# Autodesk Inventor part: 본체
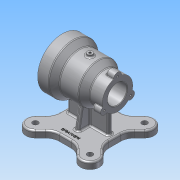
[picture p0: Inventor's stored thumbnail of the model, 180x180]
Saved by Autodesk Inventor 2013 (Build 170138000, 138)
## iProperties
Created: 2017-03
Part Number: 본체
Material: 알루미늄 6061
Document SubType Name: Modeling
Designer: Administrator
Density: 2.71 g/cm^3
Mass: 1005.19 g
Surface Area: 839.933 cm^2
Volume: 370.92 cm^3
Author: Administrator
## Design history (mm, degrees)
sketch "스케치1"
  geometry: L1 (-48, 0)-(52, 0); L2 (52, 0)-(52, 27.5); L3 (52, 27.5)-(29, 27.5); L4 (29, 27.5)-(17, 36); L5 (17, 36)-(-17, 36); L6 (-17, 36)-(-28, 45); L7 (-28, 45)-(-48, 45); L8 (-48, 45)-(-48, 0); 2 further points
  constraints: 16 end point, 3 parallel, 2 perpendicular, 1 horizontal, 1 midpoint, 1 point on line, 1 vertical alignment
  dimensions: "d9" = 55 diameter of L3 L1; "d11" = 72 diameter of L5 L1; "d12" = 90 diameter of L7 L1; "d14" = 23 distance of L2.end L3.end; "d15" = 100 distance between parallel lines of L2 L8; "d16" = 20 distance of L6.end L7.end; "d17" = 31 distance from line of L5.end L8; "d18" = 65 distance from line of L4.end L8
revolve "회전1" sketch "스케치1" stored, may be unused: angle "d19" = 90 deg
hole "구멍1" diameter "d22" = 52; stored, may be unused: countersink angle "d26" = 90 deg, drill point angle "d28" = 0 deg; dims "d20" = 10, "d21" = 10, "d23" = 6, "d24" = 70, "d25" = 23, "d27" = 70
hole "구멍2" diameter "d31" = 35; stored, may be unused: countersink angle "d35" = 90 deg, drill point angle "d37" = 0 deg; dims "d29" = 10, "d30" = 10, "d32" = 6, "d33" = 70, "d34" = 23, "d36" = 30
chamfer "모따기1" distance "d38" = 1; stored, may be unused: second distance "d39" = 2, angle "d40" = 45 deg
fillet "모깎기1" dims "d41" = 3
fillet "모깎기2" dims "d42" = 3
node "작업 평면1"
node "작업 평면3"
sketch "스케치11"
  geometry: L1 (-18.958, 45)-(22.958, 45); L2 (22.958, 45)-(39.477, 61.518); L3 (63.518, 37.477)-(47, 20.958); L4 (47, 20.958)-(47, -20.958); L5 (47, -20.958)-(63.518, -37.477); L6 (39.477, -61.518)-(22.958, -45); L7 (22.958, -45)-(-18.958, -45); L8 (-18.958, -45)-(-35.477, -61.518); L9 (-59.518, -37.477)-(-43, -20.958); L10 (-43, -20.958)-(-43, 20.958); L11 (-43, 20.958)-(-59.518, 37.477); L12 (-35.477, 61.518)-(-18.958, 45); L13 (0, 0)-(2, 0); L14 (2, 0)-(-47.497, 49.497); L15 (2, 0)-(51.497, 49.497); L16 (2, 0)-(-47.497, -49.497); L17 (2, 0)-(51.497, -49.497); A1 r 17 centre (51.497, 49.497) between (63.518, 37.477) and (39.477, 61.518); A2 r 17 centre (51.497, -49.497) between (39.477, -61.518) and (63.518, -37.477); A3 r 17 centre (-47.497, -49.497) between (-59.518, -37.477) and (-35.477, -61.518); A4 r 17 centre (-47.497, 49.497) between (-35.477, 61.518) and (-59.518, 37.477); 2 further points
  constraints: 34 end point, 8 point on circle, 8 tangent, 5 equal length, 5 perpendicular, 4 centre point, 2 equal radius, 2 parallel, 1 coincident, 1 horizontal, 1 midpoint, 1 vertical alignment
  dimensions: "d179" = 2 distance of L13.start L13.end; "d182" = 17 radius of A1; "d183" = 90 distance between parallel lines of L7 L1; "d184" = 45 distance from line of L13.end L7; "d185" = 90 distance between parallel lines of L4 L10; "d186" = 45 distance from line of L13.end L10; "d187" = 70 distance of L13.end L14.end; "d188" = 70 distance of L13.end L15.end; "d189" = 90 deg angle of L15 L14; "d191" = 70 distance of L13.end L16.end; "d192" = 70 distance of L13.end L17.end; "d193" = 90 deg angle of L15 L17; "d194" = 90 deg angle of L16 L17; "d195" = 34 distance between parallel lines of L9 L8
extrude "돌출6" join sketch "스케치11" distance "d196" = 12; taper "d197" = 0 deg
sketch "스케치3"
  geometry: C1 r 5 at (-47.497, -49.497); C2 r 5 at (51.497, -49.497); C3 r 5 at (51.497, 49.497); C4 r 5 at (-47.497, 49.497); A1 r 17 centre (-47.497, -49.497) between (-59.518, -37.477) and (-35.477, -61.518) reference; A2 r 17 centre (51.497, -49.497) between (39.477, -61.518) and (63.518, -37.477) reference; A3 r 17 centre (51.497, 49.497) between (63.518, 37.477) and (39.477, 61.518) reference; A4 r 17 centre (-47.497, 49.497) between (-35.477, 61.518) and (-59.518, 37.477) reference; 1 further point
  constraints: 4 centre point, 4 coincident, 1 equal radius
  dimensions: "d72" = 10 diameter of C1; "d198" = 10 diameter of C3; "d199" = 10 diameter of C4
extrude "돌출2" cut sketch "스케치3" distance "d74" = 12; taper "d75" = 0 deg
fillet "모깎기11" dims "d200" = 25
fillet "모깎기12" dims "d201" = 3
sketch "스케치12"
  geometry: L1 (-35, 4)-(39, 4); L2 (39, 4)-(39, -4); L3 (39, -4)-(-35, -4); L4 (-35, -4)-(-35, 4); L5 (0, 0)-(2, 0)
  constraints: 10 end point, 2 parallel, 2 perpendicular, 1 horizontal
  dimensions: "d231" = 2 distance of L5.start L5.end; "d232" = 8 distance between parallel lines of L3 L1; "d233" = 74 distance of L2.end L3.end; "d234" = 37 distance from line of L5.end L4; "d235" = 4 distance from line of L5.end L1
extrude "돌출7" join sketch "스케치12" stored distance "d207" = 12; taper "d208" = 0 deg
node "작업 평면4"
sketch "스케치14"
  geometry: L1 (-42, -70)-(-4, -70) reference; L2 (-4, -70)-(-4, -35.777) reference; L3 (4, -35.777)-(4, -70) reference; L4 (4, -70)-(42, -70) reference; L5 (45, -73)-(45, -82) reference; L6 (45, -82)-(-45, -82) reference; L7 (-45, -82)-(-45, -73) reference; L8 (-25, -70)-(-21.244, -48.697); L9 (25, -70)-(21.849, -52.131); C1 r 26 at (0, 0) reference; A1 r 3 centre (-42, -73) between (-42, -70) and (-45, -73) reference; A2 r 36 centre (0, 0) between (4, -35.777) and (-4, -35.777) reference; A3 r 3 centre (42, -73) between (45, -73) and (42, -70) reference; 1 further point
  constraints: 4 end point, 2 point on line
  dimensions: "d237" = 25 horizontal distance of point (0, 0) L9.start; "d238" = 25 horizontal distance of point (0, 0) L8.start; "d239" = 100 deg angle of L4 L9; "d240" = 100 deg angle of L1 L8
  node "절단 모서리 투영3"
feature "리브5" dims "d241" = 1, "d242" = 8, "d243" = 0, "d244" = 0, "d245" = 1, "d246" = 1
feature "리브6" dims "d247" = 1, "d248" = 8, "d249" = 0, "d250" = 0, "d251" = 1, "d252" = 1
fillet "모깎기15" dims "d253" = 3
fillet "모깎기16" dims "d254" = 3
sketch "스케치6"
  geometry: A1 r 27.5 centre (0, 0) between (-27.5, 0) and (-26.609, -6.943) reference; A2 r 7 centre (-27.5, 0) between (-26.609, 6.943) and (-26.609, -6.943)
  constraints: 5 point on circle, 1 centre point, 1 horizontal alignment
  dimensions: "d104" = 7 radius of A2
extrude "돌출4" join sketch "스케치6" distance "d106" = 15; taper "d107" = 0 deg
sketch "스케치7"
  geometry: A1 r 7 centre (0, 0) between (0.891, 6.943) and (0.891, -6.943) reference; 1 further point
  constraints: 1 coincident
hole "구멍3" sketch "스케치7" at (0, 0) diameter "d108" = 3.242; stored, may be unused: countersink angle "d112" = 90 deg, drill point angle "d114" = 118 deg; dims "d109" = 9, "d110" = 70, "d111" = 23, "d113" = 11
fillet "모깎기8" dims "d116" = 3
fillet "모깎기7" dims "d115" = 1
sketch "스케치8"
  geometry: C1 r 45 at (0, 0) reference; 1 further point
  constraints: 1 horizontal alignment
  dimensions: "d120" = 40 distance of C1.centre point (40, 0)
hole "구멍4" sketch "스케치8" at (40, 0) diameter "d121" = 3.242; stored, may be unused: countersink angle "d125" = 90 deg, drill point angle "d127" = 118 deg; dims "d122" = 9, "d123" = 70, "d124" = 23, "d126" = 11
node "작업 평면2"
sketch "스케치9"
  geometry: L1 (-48, -45)-(-48, 45) reference; C1 r 5 at (2, 0); 1 further point
  constraints: 1 centre point, 1 horizontal alignment
  dimensions: "d152" = 50 distance from line of L1 C1.centre; "d153" = 10 diameter of C1
extrude "돌출5" join sketch "스케치9" stored distance "d134" = 15; taper "d135" = 0 deg
hole "구멍6" diameter "d156" = 4.134; stored, may be unused: countersink angle "d160" = 90 deg, drill point angle "d162" = 0 deg; dims "d154" = 10, "d155" = 10, "d157" = 9, "d158" = 70, "d159" = 23, "d161" = 20
fillet "모깎기10" dims "d163" = 3
sketch "스케치13"
  geometry: L1 (47, -10.603)-(47, 10.603) reference; 2 further points
  constraints: 1 other
  dimensions: "d227" = 35 vertical distance of point (0, 0) point (2, -35); "d228" = 45 distance from line of L1 point (2, -35)
feature "엠보싱2" sketch "스케치13" dims "d229" = 0.5, "d230" = 0
node "솔리드1"
pattern_circular "원형 패턴1" dims "d118" = 360 deg
pattern_circular "원형 패턴2" dims angle "d129" = 360 deg
other parameters: "d43" = -82, "d50" = 17, "d57" = 17, "d62" = 17, "d64" = 17, "d178" = -82, "d236" = 2
